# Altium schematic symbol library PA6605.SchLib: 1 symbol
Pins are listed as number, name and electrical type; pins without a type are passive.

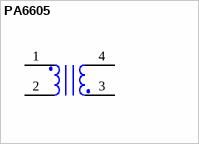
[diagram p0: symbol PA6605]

## PA6605
designator X?, comment PA6605-AL
Manufacturer: Coilcraft Inc; SymbolVersion: use current date i.e. 2008-05-20; SymbolCreator: Use a-id; CompType: Transformer; U/M: EA, IN, or GM
pins: 1, 2, 3, 4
